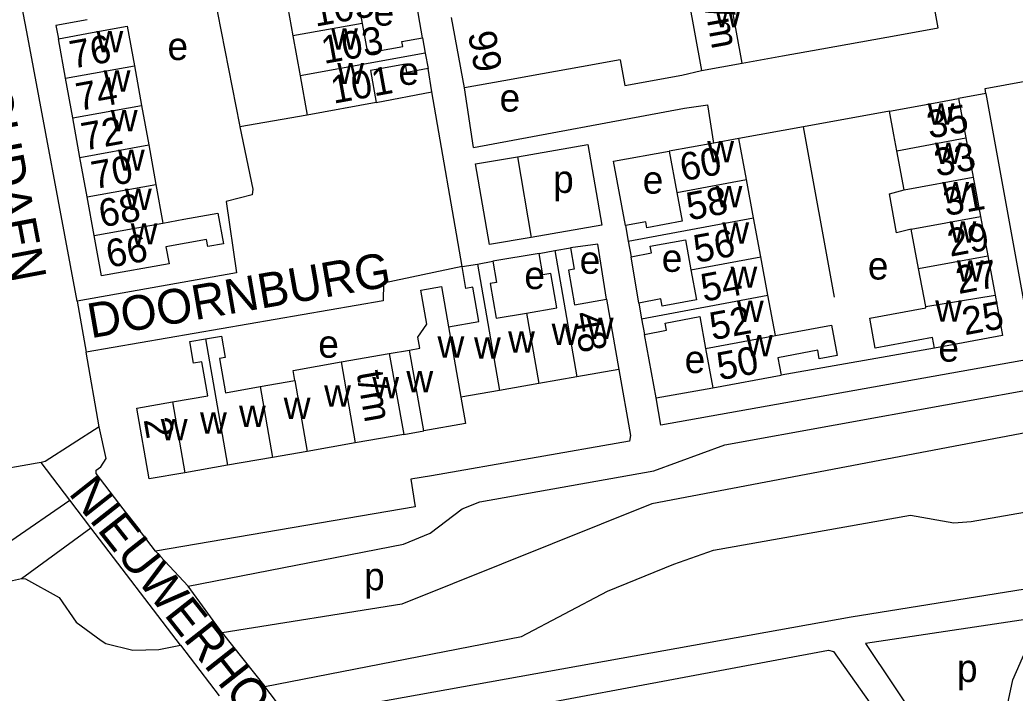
# Model space of a CAD drawing. Extents: x 157794 to 159375, y 380877 to 382306.
# Drawn here: x 158508.3 to 158651.8, y 381345.1 to 381442.2 of the extents above; entities that cross this region are included whole.
import ezdxf

# ---------------------------------------------------------------- set-up
doc = ezdxf.new("R2010")
doc.units = 0
for name, color, linetype in [('BLT_Basislijn', 7, 'Continuous'), ('BLT_Bebouwing', 7, 'Continuous'), ('BLT_Centroide', 7, 'Continuous'), ('BLT_Huisnummer', 7, 'Continuous'), ('BLT_Huisnummer_ tussenligend', 7, 'Continuous'), ('BLT_Huisnummer_reeks', 7, 'Continuous'), ('BLT_Onderdoorgang_en_onderverdeling', 7, 'Continuous'), ('BLT_Onderverdeling_panden', 7, 'Continuous'), ('BLT_Straatnaam', 7, 'Continuous')]:
    doc.layers.add(name, color=color, linetype=linetype)

msp = doc.modelspace()

# ---------------------------------------------------------------- linework, layer by layer
at = {"layer": 'BLT_Basislijn'}
for p, q in [((158566.34, 381439.63), (158565.18, 381446.36)), ((158567.72, 381431.83), (158567.15, 381435.18)), ((158559.69, 381430.28), (158567.72, 381431.83)), ((158572.06, 381406.61), (158567.72, 381431.83)), ((158573.71, 381423.78), (158572.39, 381432.39)), ((158647.61, 381431.59), (158643.66, 381430.86)), ((158608.38, 381424.44), (158607.5, 381429.98)), ((158633.72, 381429.02), (158621.3, 381426.79)), ((158549.74, 381428.47), (158540.01, 381426.77)), ((158621.3, 381426.79), (158611.98, 381425.11)), ((158625.75, 381402.23), (158621.3, 381426.79)), ((158574.01, 381421.44), (158580.04, 381422.47)), ((158580.04, 381422.47), (158582.03, 381410.84)), ((158583.17, 381408.52), (158576.5, 381407.38)), ((158597.55, 381401.35), (158596.45, 381408.05)), ((158516.54, 381401.63), (158517.87, 381394.27)), ((158600.03, 381387.7), (158598.38, 381396.84)), ((158640.19, 381394.86), (158618.09, 381390.96)), ((158519.71, 381383.5), (158517.87, 381394.27)), ((158600.03, 381387.7), (158608.24, 381389.13)), ((158509.46, 381378.03), (158485.08, 381373.71)), ((158510.78, 381378.26), (158509.46, 381378.03)), ((158511.35, 381378.38), (158510.78, 381378.26)), ((158515.5, 381372.92), (158511.35, 381378.38)), ((158567.64, 381376.44), (158564.68, 381375.93)), ((158518.54, 381368.94), (158515.5, 381372.92)), ((158508.53, 381361.64), (158518.54, 381368.94)), ((158531.45, 381352), (158518.54, 381368.94)), ((158527.86, 381365.57), (158532.57, 381360.5)), ((158497.19, 381359.04), (158508.53, 381361.64)), ((158537.44, 381353.78), (158543.6, 381346.05)), ((158531.45, 381352), (158537.03, 381344.71)), ((158547.12, 381341.48), (158543.6, 381346.05))]:
    msp.add_line(p, q, dxfattribs=at)
for points in [[(158516.54, 381401.63), (158509.27, 381440.5), (158504.49, 381465.23)], [(158536.93, 381445.22), (158536.78, 381443.23), (158539.94, 381427.07), (158540.01, 381426.77)], [(158518.01, 381442.24), (158513.5, 381441.42), (158513.86, 381439.49)], [(158731.89, 381437.96), (158745.99, 381415.56), (158754.2, 381384.48), (158754.07, 381380.8), (158752.23, 381379.3), (158750.76, 381379.18), (158735.9, 381381.6), (158689.67, 381369.9), (158688.01, 381367.9), (158680.38, 381366.01), (158668.53, 381362.54), (158628.16, 381356.06), (158547.12, 381341.48)], [(158647.61, 381431.59), (158647.48, 381432.3), (158665.85, 381435.67)], [(158647.61, 381431.59), (158653.76, 381397.73), (158653.98, 381393.26), (158600.74, 381383.75), (158600.03, 381387.7)], [(158573.71, 381423.78), (158604.14, 381429.46), (158607.5, 381429.98)], [(158540.01, 381426.77), (158541.87, 381417.79), (158541.78, 381416.96), (158538.03, 381416.01), (158539.55, 381405.7), (158516.54, 381401.63)], [(158580.04, 381422.47), (158590.21, 381424.22), (158592.21, 381412.59), (158582.03, 381410.84)], [(158595.61, 381412.55), (158593.89, 381421.85), (158601.93, 381423.25)], [(158582.03, 381410.84), (158576.01, 381409.8), (158574.01, 381421.44)], [(158592.88, 381401.92), (158591.62, 381409.87), (158587.7, 381409.31)], [(158572.06, 381406.61), (158560.75, 381404.24), (158560.67, 381401.68), (158517.87, 381394.27)], [(158543.6, 381346.05), (158580.62, 381353.26), (158593.04, 381359.81), (158602.61, 381363.71), (158608.33, 381365.69), (158636.75, 381370.78), (158642.99, 381369.67), (158645.5, 381369.83), (158747.1, 381387.65), (158747.53, 381387.99), (158746.49, 381393.1), (158745.35, 381396.47), (158737.83, 381401.19), (158735.65, 381402.15), (158732.99, 381401.78)], [(158594.65, 381391.76), (158596.37, 381382.25), (158596.21, 381381.45), (158567.64, 381376.44)], [(158532.57, 381360.5), (158563.6, 381366.56), (158567.48, 381368.15), (158572.09, 381371.68), (158574.64, 381372.66), (158599.71, 381377.14), (158609.96, 381380.91), (158657.67, 381389.58), (158658.9, 381389.68)], [(158659.48, 381386.05), (158657.53, 381384.28), (158655.56, 381383.06), (158599.44, 381372.38), (158563.36, 381357.9), (158537.44, 381353.78)], [(158519.71, 381383.5), (158511.95, 381378.49), (158511.35, 381378.38)], [(158527.86, 381365.57), (158519.27, 381376.79), (158519.27, 381377.27), (158519.97, 381377.75), (158520.72, 381378.91), (158519.71, 381383.5)], [(158564.68, 381375.93), (158565.32, 381371.96), (158527.86, 381365.57)], [(158485.08, 381373.71), (158491.07, 381362.99), (158507.01, 381367.04), (158515.5, 381372.92)], [(158508.53, 381361.64), (158509.08, 381361.56), (158513.97, 381358.9), (158516.39, 381355.3), (158519.99, 381352.67), (158520.68, 381352.26), (158524.57, 381351.28), (158528.32, 381351.36), (158531.45, 381352)], [(158537.44, 381353.78), (158532.57, 381360.5)], [(158657.5, 381356.32), (158630.22, 381352.22), (158646.6, 381327.82), (158648.47, 381328.62), (158651.27, 381330.92), (158650.42, 381335.7), (158650.42, 381342.06), (158651.48, 381346.99), (158653.39, 381351.38), (158656.74, 381355.68), (158657.5, 381356.32)], [(158581.73, 381343.22), (158624.92, 381351.29), (158625.62, 381351.08), (158636.33, 381335.94)]]:
    msp.add_lwpolyline(points, dxfattribs=at)
at = {"layer": 'BLT_Bebouwing'}
for p, q in [((158546.68, 381445.33), (158547.67, 381439.9)), ((158572.39, 381432.39), (158570.55, 381442.56)), ((158514.89, 381433.79), (158513.86, 381439.49)), ((158547.67, 381439.9), (158548.71, 381434.14)), ((158566.34, 381439.63), (158566.74, 381437.41)), ((158623.94, 381438.03), (158629.55, 381439.04)), ((158629.55, 381439.04), (158635.17, 381440.06)), ((158566.74, 381437.41), (158567.15, 381435.18)), ((158618.29, 381437.01), (158623.94, 381438.03)), ((158594.86, 381436.45), (158589.27, 381435.44)), ((158606.6, 381434.89), (158612.45, 381435.95)), ((158612.45, 381435.95), (158618.29, 381437.01)), ((158524.8, 381435.58), (158525.84, 381429.88)), ((158589.27, 381435.44), (158583.67, 381434.42)), ((158515.92, 381428.09), (158514.89, 381433.79)), ((158548.71, 381434.14), (158549.74, 381428.47)), ((158578.07, 381433.41), (158572.39, 381432.39)), ((158583.67, 381434.42), (158578.07, 381433.41)), ((158559.69, 381430.28), (158549.74, 381428.47)), ((158643.66, 381430.86), (158644.72, 381425.19)), ((158525.84, 381429.88), (158526.87, 381424.18)), ((158516.95, 381422.38), (158515.92, 381428.09)), ((158611.98, 381425.11), (158608.38, 381424.44)), ((158613.07, 381419.19), (158611.98, 381425.11)), ((158644.72, 381425.19), (158645.77, 381419.52)), ((158526.87, 381424.18), (158527.9, 381418.48)), ((158608.38, 381424.44), (158601.93, 381423.25)), ((158601.93, 381423.25), (158603.03, 381417.32)), ((158635.8, 381417.68), (158634.75, 381423.34)), ((158517.99, 381416.68), (158516.95, 381422.38)), ((158614.1, 381413.66), (158613.07, 381419.19)), ((158645.77, 381419.52), (158646.83, 381413.85)), ((158527.9, 381418.48), (158528.91, 381412.89)), ((158519, 381411.1), (158517.99, 381416.68)), ((158615.15, 381408.04), (158614.1, 381413.66)), ((158646.83, 381413.85), (158647.88, 381408.18)), ((158595.61, 381412.55), (158596.03, 381410.3)), ((158637.9, 381406.34), (158636.85, 381412.01)), ((158596.03, 381410.3), (158596.45, 381408.05)), ((158583.17, 381408.52), (158585.44, 381408.92)), ((158585.44, 381408.92), (158587.7, 381409.31)), ((158574.28, 381406.99), (158576.5, 381407.38)), ((158616.18, 381402.48), (158615.15, 381408.04)), ((158647.88, 381408.18), (158648.93, 381402.52)), ((158572.06, 381406.61), (158574.28, 381406.99)), ((158638.92, 381400.86), (158637.9, 381406.34)), ((158592.88, 381401.92), (158594.65, 381391.76)), ((158617.26, 381396.67), (158616.18, 381402.48)), ((158597.55, 381401.35), (158597.96, 381399.1)), ((158597.96, 381399.1), (158598.38, 381396.84)), ((158607.19, 381394.8), (158608.24, 381389.13)), ((158594.65, 381391.76), (158588.61, 381390.71)), ((158542.95, 381389.3), (158547.96, 381390.17)), ((158588.61, 381390.71), (158583.13, 381389.75)), ((158608.24, 381389.13), (158618.09, 381390.96)), ((158577.46, 381388.76), (158571.89, 381387.79)), ((158583.13, 381389.75), (158577.46, 381388.76)), ((158563.65, 381382.39), (158556.65, 381381.17)), ((158549.74, 381379.96), (158544.73, 381379.09)), ((158556.65, 381381.17), (158549.74, 381379.96)), ((158544.73, 381379.09), (158538.25, 381377.95)), ((158538.25, 381377.95), (158532.06, 381376.87))]:
    msp.add_line(p, q, dxfattribs=at)
for points in [[(158565.18, 381446.36), (158562.23, 381445.82), (158562.04, 381446.88), (158556.88, 381445.94), (158557.64, 381441.7)], [(158635.17, 381440.06), (158640.71, 381441.06), (158640.04, 381444.78)], [(158557.64, 381441.7), (158558.41, 381437.47), (158563.52, 381438.39), (158563.39, 381439.1), (158566.34, 381439.63)], [(158513.86, 381439.49), (158518.71, 381440.37), (158523.77, 381441.29), (158524.8, 381435.58)], [(158594.86, 381436.45), (158595.52, 381432.76), (158603.75, 381434.24)], [(158567.15, 381435.18), (158564.11, 381434.64), (158563.9, 381435.82), (158558.86, 381434.9), (158559.69, 381430.28)], [(158603.75, 381434.24), (158606.6, 381434.89)], [(158633.72, 381429.02), (158638.74, 381429.95), (158643.66, 381430.86)], [(158634.75, 381423.34), (158634.32, 381425.65), (158633.72, 381429.02)], [(158603.03, 381417.32), (158603.81, 381413.16), (158598.73, 381412.21), (158598.56, 381413.1), (158595.61, 381412.55)], [(158636.85, 381412.01), (158634.72, 381411.51), (158633.68, 381417.13), (158635.8, 381417.68)], [(158528.91, 381412.89), (158531.92, 381413.44), (158536.84, 381414.33), (158537.64, 381409.91), (158535.38, 381409.5), (158535.19, 381410.55), (158529.35, 381409.49), (158529.8, 381407.04), (158520.05, 381405.27), (158519, 381411.1)], [(158596.45, 381408.05), (158599.36, 381408.6), (158599.18, 381409.55), (158604.27, 381410.5), (158605.07, 381406.16)], [(158587.7, 381409.31), (158588.24, 381406.26), (158587.4, 381406.12), (158588.27, 381401.11), (158592.88, 381401.92)], [(158576.5, 381407.38), (158577.03, 381404.32), (158576.11, 381404.16), (158576.98, 381399.16), (158581.36, 381399.92)], [(158581.36, 381399.92), (158585.74, 381400.69), (158584.87, 381405.64), (158583.71, 381405.44), (158583.17, 381408.52)], [(158570.12, 381397.94), (158574.5, 381398.71), (158573.63, 381403.66), (158572.6, 381403.48), (158572.06, 381406.61)], [(158605.07, 381406.16), (158605.88, 381401.83), (158600.94, 381400.91), (158600.74, 381401.95), (158597.55, 381401.35)], [(158564.48, 381394.58), (158565.96, 381394.84), (158565.67, 381396.46), (158566.97, 381398.32), (158566.11, 381403.23), (158569.11, 381403.75), (158570.12, 381397.94)], [(158648.93, 381402.52), (158650.02, 381396.69), (158640.19, 381394.86)], [(158640.19, 381394.86), (158639.91, 381396.38), (158631.65, 381394.84), (158630.85, 381399.17), (158638.96, 381400.67), (158638.92, 381400.86)], [(158598.38, 381396.84), (158601.52, 381397.43), (158601.33, 381398.48), (158606.34, 381399.41), (158607.19, 381394.8)], [(158617.26, 381396.67), (158625.36, 381398.18), (158626.17, 381393.8), (158623.57, 381393.31), (158623.35, 381394.54), (158617.62, 381393.48), (158618.09, 381390.96)], [(158530.28, 381387.09), (158535.4, 381387.98), (158534.54, 381392.9), (158533.33, 381392.69), (158532.78, 381395.8), (158535.07, 381396.2)], [(158535.07, 381396.2), (158537.35, 381396.59), (158537.89, 381393.52), (158537.07, 381393.38), (158537.93, 381388.42), (158542.95, 381389.3)], [(158561.53, 381394.06), (158564.48, 381394.58)], [(158554.62, 381392.86), (158561.53, 381394.06)], [(158547.96, 381390.17), (158547.7, 381391.65), (158554.62, 381392.86)], [(158571.89, 381387.79), (158572.55, 381383.99), (158566.53, 381382.94)], [(158532.06, 381376.87), (158526.94, 381375.98), (158525.15, 381386.2), (158530.28, 381387.09)], [(158563.65, 381382.39), (158566.53, 381382.94)]]:
    msp.add_lwpolyline(points, dxfattribs=at)
at = {"layer": 'BLT_Onderdoorgang_en_onderverdeling'}
for points in [[(158566.53, 381382.94), (158564.48, 381394.58)], [(158561.53, 381394.06), (158563.65, 381382.39)]]:
    msp.add_lwpolyline(points, dxfattribs=at)
at = {"layer": 'BLT_Onderverdeling_panden'}
for p, q in [((158612.45, 381435.95), (158610.37, 381447.45)), ((158604.52, 381446.39), (158606.6, 381434.89)), ((158557.64, 381441.7), (158547.67, 381439.9)), ((158566.74, 381437.41), (158548.71, 381434.14)), ((158514.89, 381433.79), (158524.8, 381435.58)), ((158515.92, 381428.09), (158525.84, 381429.88)), ((158634.75, 381423.34), (158644.72, 381425.19)), ((158516.95, 381422.38), (158526.87, 381424.18)), ((158603.03, 381417.32), (158613.07, 381419.19)), ((158635.8, 381417.68), (158645.77, 381419.52)), ((158517.99, 381416.68), (158527.9, 381418.48)), ((158596.03, 381410.3), (158614.1, 381413.66)), ((158636.85, 381412.01), (158646.83, 381413.85)), ((158519, 381411.1), (158528.91, 381412.89)), ((158585.44, 381408.92), (158588.61, 381390.71)), ((158605.07, 381406.16), (158615.15, 381408.04)), ((158637.9, 381406.34), (158647.88, 381408.18)), ((158574.28, 381406.99), (158577.46, 381388.76)), ((158597.96, 381399.1), (158616.18, 381402.48)), ((158638.92, 381400.86), (158648.93, 381402.52)), ((158581.36, 381399.92), (158583.13, 381389.75)), ((158570.12, 381397.94), (158571.89, 381387.79)), ((158535.07, 381396.2), (158538.25, 381377.95)), ((158607.19, 381394.8), (158617.26, 381396.67)), ((158554.62, 381392.86), (158556.65, 381381.17)), ((158547.96, 381390.17), (158549.74, 381379.96)), ((158542.95, 381389.3), (158544.73, 381379.09)), ((158530.28, 381387.09), (158532.06, 381376.87))]:
    msp.add_line(p, q, dxfattribs=at)

# ---------------------------------------------------------------- texts
at = {"layer": 'BLT_Centroide'}
for s, p in [('e', (158559.3, 381441.38)), ('w', (158608.48, 381441.16)), ('w', (158519.33, 381437.53)), ('w', (158553.18, 381437.94)), ('e', (158529.58, 381436.42)), ('w', (158554.06, 381432.94)), ('e', (158562.88, 381432.84)), ('w', (158520.37, 381431.84)), ('e', (158577.47, 381428.98)), ('w', (158521.4, 381426.12)), ('w', (158639.21, 381427.09)), ('w', (158607.42, 381421.66)), ('w', (158640.27, 381421.44)), ('w', (158522.43, 381420.44)), ('p', (158585.19, 381417.25)), ('e', (158598.11, 381417.14)), ('w', (158641.31, 381415.75)), ('w', (158523.45, 381414.78)), ('w', (158608.62, 381415.19)), ('w', (158609.59, 381409.91)), ('w', (158642.36, 381410.09)), ('w', (158524.27, 381409.81)), ('e', (158589.02, 381405.58)), ('e', (158600.86, 381405.86)), ('e', (158630.58, 381404.75)), ('w', (158643.42, 381404.44)), ('e', (158581.04, 381403.38)), ('w', (158610.77, 381403.56)), ('w', (158611.69, 381398.62)), ('w', (158640.29, 381398.69)), ('w', (158590.05, 381396.19)), ('w', (158578.7, 381394.22)), ('w', (158584.98, 381395.31)), ('e', (158551.32, 381393.47)), ('w', (158568.52, 381393.47)), ('w', (158573.78, 381393.36)), ('w', (158613, 381393.66)), ('e', (158640.76, 381392.91)), ('e', (158604.16, 381391.26)), ('w', (158564.03, 381388.48)), ('w', (158559.12, 381387.62)), ('w', (158552.17, 381386.41)), ('w', (158546.34, 381384.62)), ('w', (158539.89, 381383.5)), ('w', (158528.61, 381381.55)), ('w', (158534.27, 381382.52)), ('p', (158557.93, 381359.93)), ('p', (158643.43, 381346.68))]:
    msp.add_text(s, height=4, dxfattribs=at).set_placement(p)
at = {"layer": 'BLT_Huisnummer'}
for s, rotation, p in [('105', 10.2734, (158550.91, 381441.22)), ('101', 10.2734, (158553.52, 381430.11)), ('74', 10.2748, (158516.77, 381429.07)), ('35', 10.5253, (158639.48, 381425.06)), ('60', 10.5279, (158603.88, 381418.93)), ('70', 10.2748, (158518.98, 381417.77)), ('29', 10.5253, (158642.45, 381408.03)), ('66', 10.2748, (158521.11, 381406.44)), ('54', 10.5279, (158606.89, 381401.53)), ('25', 10.5253, (158644.56, 381396.7)), ('50', 10.5279, (158609.2, 381390.2))]:
    msp.add_text(s, height=4, rotation=rotation, dxfattribs=at).set_placement(p)
at = {"layer": 'BLT_Huisnummer_ tussenligend'}
for s, rotation, p in [('103', 10.2734, (158552.15, 381435.85)), ('76', 10.2748, (158515.85, 381435.16)), ('72', 10.2748, (158517.53, 381423.33)), ('33', 10.5253, (158640.53, 381419.59)), ('58', 10.5279, (158604.8, 381413.27)), ('31', 10.5253, (158641.85, 381413.89)), ('68', 10.2748, (158520.06, 381412.26)), ('56', 10.5279, (158605.84, 381407.14)), ('27', 10.5253, (158643.67, 381402.65)), ('52', 10.5279, (158608.16, 381395.98))]:
    msp.add_text(s, height=4, rotation=rotation, dxfattribs=at).set_placement(p)
at = {"layer": 'BLT_Huisnummer_reeks'}
for s, rotation, p in [('t/m', 280.2574, (158606.84, 381445.15)), ('99', 280.275, (158572.89, 381440.27)), ('48', 279.8982, (158588.09, 381399.84)), ('t/m', 279.8949, (158556.83, 381391.29)), ('2', 279.8899, (158526.13, 381384.54))]:
    msp.add_text(s, height=4, rotation=rotation, dxfattribs=at).set_placement(p)
at = {"layer": 'BLT_Straatnaam'}
for s, rotation, p in [('OUDAEN', 280.7856, (158501.93, 381432.22)), ('DOORNBURG', 9.87, (158518.52, 381396.27)), ('NIEUWERHOEK', 308.2501, (158515.19, 381373.88))]:
    msp.add_text(s, height=5, rotation=rotation, dxfattribs=at).set_placement(p)

doc.saveas('drawing.dxf')
